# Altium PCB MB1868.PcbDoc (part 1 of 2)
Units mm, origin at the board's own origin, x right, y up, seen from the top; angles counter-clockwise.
Board outline 59.55 x 30 mm, 2 copper layers (Top Layer, Bottom Layer), stack 1.499 mm thick; 74 components, 54 nets, 296 pads, 368 vias.
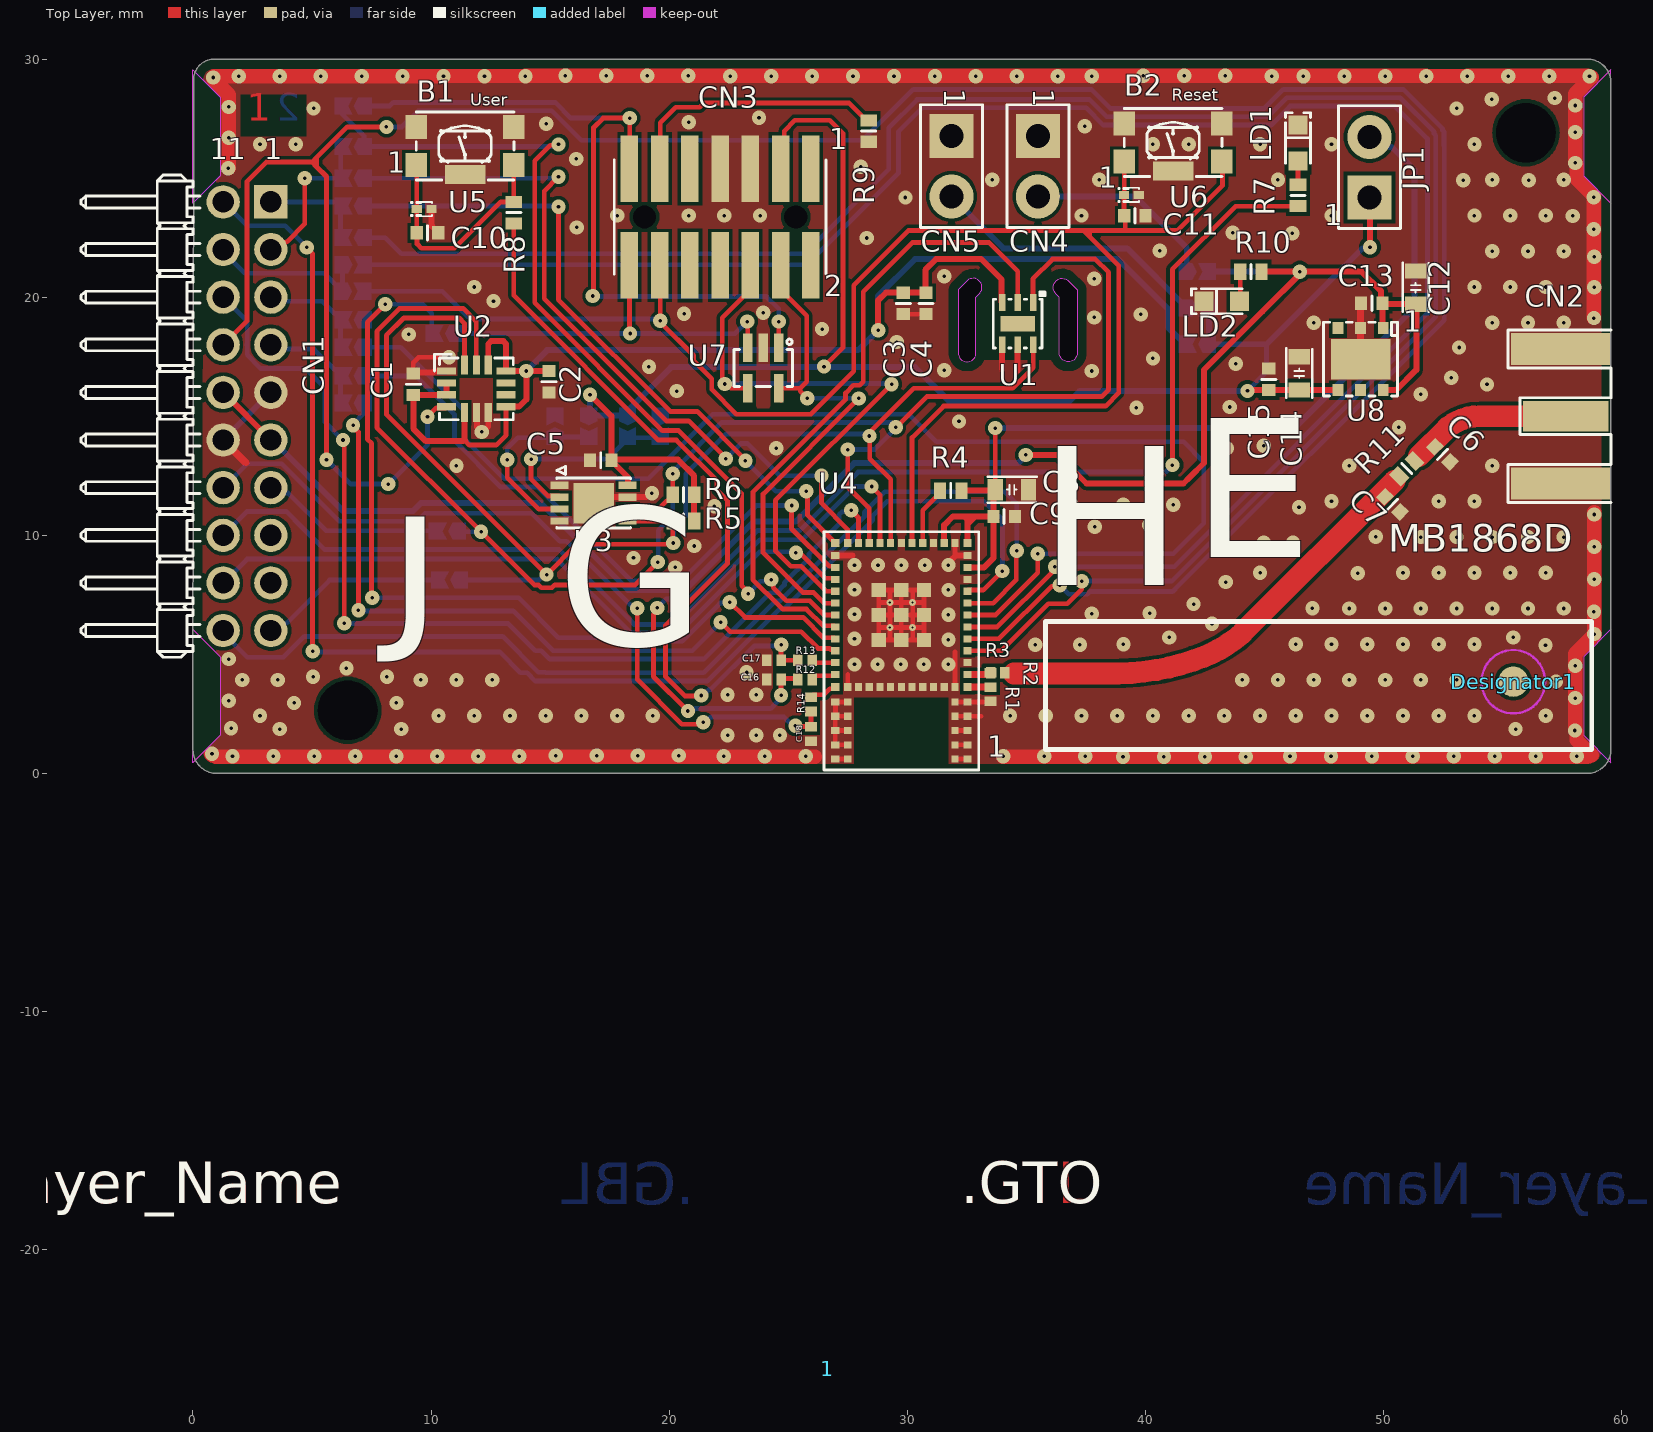
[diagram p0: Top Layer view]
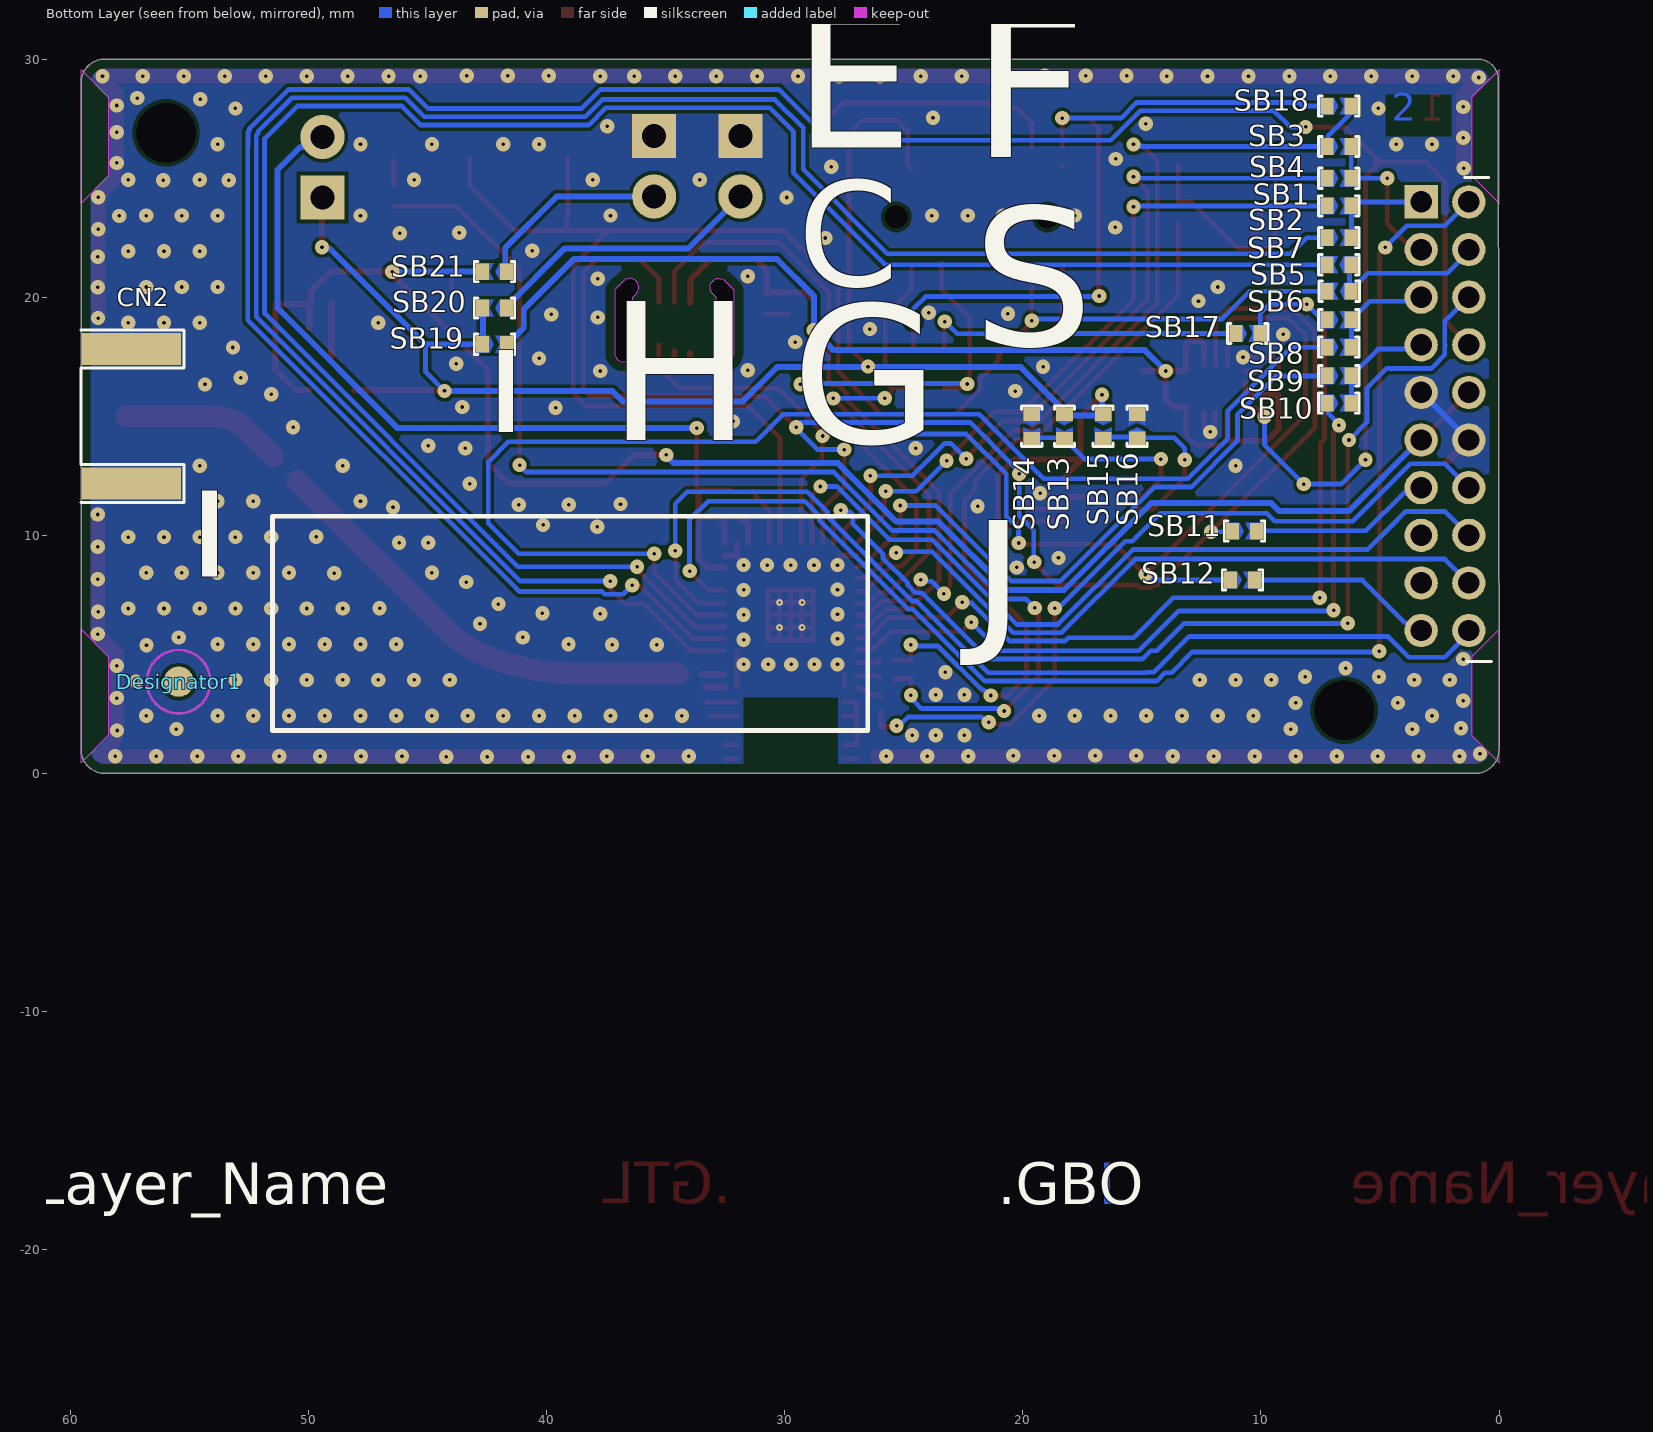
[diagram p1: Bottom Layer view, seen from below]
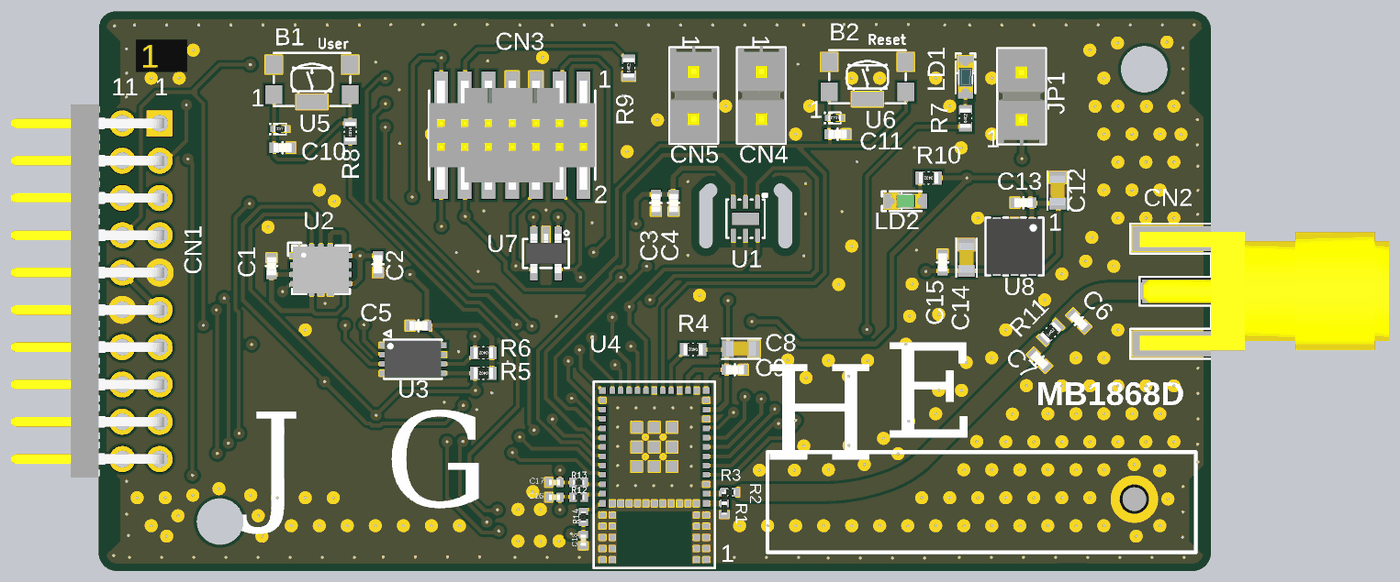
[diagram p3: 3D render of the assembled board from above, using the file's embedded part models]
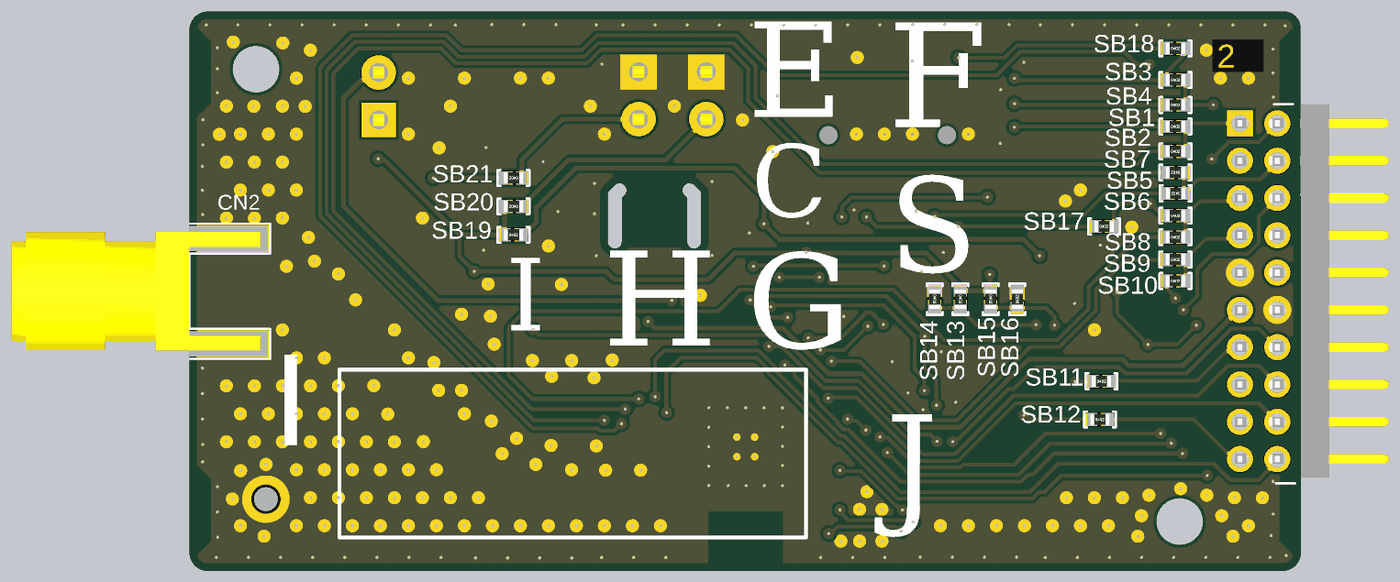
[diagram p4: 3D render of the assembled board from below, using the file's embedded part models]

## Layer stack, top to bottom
Top Solder: solder mask 0.02, Solder Resist, Dk 4.2
Top Layer: signal copper 0.0175
Dielectric 2: core 1.464, 8 x 7628, Dk 4.2
Bottom Layer: signal copper 0.0175
Bottom Solder: solder mask 0.02, Solder Resist, Dk 4.2

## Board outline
0,1 0.025,29.124 cw(c0.902,29.124) 0.902,30 58.55,30 cw(c58.55,29) 59.55,29 59.55,1 cw(c58.55,1) 58.55,0 1,0 cw(c1,1)
cut-out: 32.884,20.007 33.024,20.147 ccw(c32.759,20.412) 33.134,20.412 ccw(c32.772,20.412) 33.028,20.668 32.984,20.712 ccw(c32.803,20.531) 32.803,20.787 32.759,20.787 ccw(c32.759,20.412) 32.494,20.677 32.134,20.317 32.134,17.662 ccw(c32.509,17.662) 32.509,17.287 ccw(c32.509,17.662) 32.884,17.662
cut-out: 36.384,20.007 36.244,20.147 cw(c36.509,20.412) 36.134,20.412 cw(c36.496,20.412) 36.24,20.668 36.284,20.712 cw(c36.465,20.531) 36.465,20.787 36.509,20.787 cw(c36.509,20.412) 36.774,20.677 37.134,20.317 37.134,17.662 cw(c36.759,17.662) 36.759,17.287 cw(c36.759,17.662) 36.384,17.662

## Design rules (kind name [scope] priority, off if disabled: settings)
BoardOutlineClearance [All and not (InComponent('CN1', 'CN2') or IsText)] p1: gap=0.4 ignorepadtopadclearanceinfootprint=FALSE
Clearance Clearance_Keepout [IsKeepout] p1: gap=0 ignorepadtopadclearanceinfootprint=TRUE
Clearance Clearance_RF_SINGLE-50R_L1-2 [InNetClass('NC_RF_SINGLE-50R_L1-2')] p2: gap=0.2 ignorepadtopadclearanceinfootprint=TRUE except(0.15: SMDPad-SMDPad SMDPad-Region; 0.17: Region-Region)
Clearance Clearance_Default [All] p3: gap=0.15 ignorepadtopadclearanceinfootprint=TRUE
ComponentClearance [All] p1 off: gap=0.025 collisioncheckmode=3 verticalgap=2540 showdistances=TRUE
FanoutControl Fanout_BGA [IsBGA] p1: bgadir=Out bgaviamode=Closest fanoutstyle=Auto fanoutdirection=Alternating viagrid=0.025 // Fanout_BGA (Default Rule)
FanoutControl Fanout_LCC [IsLCC] p2: bgadir=Out bgaviamode=Closest fanoutstyle=Auto fanoutdirection=Alternating viagrid=0.025 // Fanout_LCC (Default Rule)
FanoutControl Fanout_SOIC [IsSOIC] p3: bgadir=Out bgaviamode=Closest fanoutstyle=Auto fanoutdirection=Alternating viagrid=0.025 // Fanout_SOIC (Default Rule)
FanoutControl Fanout_Small [(CompPinCount < 5)] p4: bgadir=Out bgaviamode=Closest fanoutstyle=Auto fanoutdirection=OutThenIn viagrid=0.025 // Fanout_Small (Default Rule)
FanoutControl Fanout_Default [All] p5: bgadir=Out bgaviamode=Closest fanoutstyle=Auto fanoutdirection=Alternating viagrid=0.025 // Fanout_Default (Default Rule)
Height [All] p1 off: minheight=0 maxheight=100 prefheight=0.5
HoleSize [All] p1: absolutevalues=TRUE maxlimit=10 minlimit=0.1 maxpercent=80.000 minpercent=20.000
HoleToHoleClearance [All] p1: gap=0.25 allowstackedmicrovias=TRUE
MinimumSolderMaskSliver [All] p1: minsoldermaskwidth=0.1
PlaneClearance [All] p1: clearance=0.6
PolygonConnect PolygonConnect__Default [All] p1: connectstyle=Direct reliefconductorwidth=0.3 reliefentries=2 polygonreliefangle="90 Angle" airgapwidth=0.3
RoutingVias [All] p1: holewidth=0.15 width=0.5 viastyle="Through Hole" minholewidth=0.1 minwidth=0.3 maxholewidth=0.3 maxwidth=0.6
SilkToSilkClearance [All] p1: silktosilkclearance=0.05
SilkToSolderMaskClearance [IsPad] p1: minsilkscreentomaskgap=0.05 clearancetoexposedcopper=TRUE
SolderMaskExpansion SolderMaskExpansion_Via [IsVia] p1: expansion=0.075 istentingtop=FALSE soldermaskfromhole=TRUE
SolderMaskExpansion [All] p2: expansion=0.05 istentingtop=FALSE
UnRoutedNet [All] p1: checkbadconnections=TRUE
Width Width_RF_SINGLE-50R_L1-2 [InNetClass('NC_RF_SINGLE-50R_L1-2')] p1: maxlimit=0.914 minlimit=0.3 preferedwidth=0.914 minimp=50.000000 maximp=50.000000 favimp=50.000000
Width Width_ALIMS [InNetClass('NC_POWERS')] p2: maxlimit=10 minlimit=0.2 preferedwidth=0.3
Width Width_Default [All] p3: maxlimit=10 minlimit=0.2 preferedwidth=0.2
16 further rules are at their usual default settings.

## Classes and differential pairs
component class "U_STMOD+ interface": CN1 SB1 SB2 SB3 SB4 SB5 SB6 SB7 SB8 SB9 SB10 SB11 SB12
component class U_STM32WB1M: B1 B2 C6 C7 C8 C9 C10 C11 C16 C17 C18 CN2 HW20 LD1 R1 R2 R3 R4 R5 R6 R7 R8 R11 R12 R13 R14 SB17 SB18 U4 U5 U6
component class U_Mems: C1 C2 C3 C4 C5 SB13 SB14 SB15 SB16 U1 U2 U3
component class "U_Board supply": C12 C13 C14 C15 CN3 CN4 CN5 HW5 HW6 JP1 LD2 R9 R10 SB19 SB20 SB21 U7 U8

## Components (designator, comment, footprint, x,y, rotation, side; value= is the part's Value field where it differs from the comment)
1 "Comment" Sheetbox_2L2S -18.45,-30.35 r0 top
B1 "" SWI_C&K_Y78B23110FP__ITT_KMR231GLFS 11.425,26.35 r180 top value=KMR231GLFS
B2 "" SWI_C&K_Y78B23110FP__ITT_KMR231GLFS 41.159,26.497 r180 top value=KMR231GLFS
C1 "Capacitor" C0402 9.255,16.345 r270 top value=100nF
C2 "Capacitor" C0402 14.95,16.45 r90 top value=100nF
C3 "Capacitor" C0402 29.834,19.737 r90 top value=2.2uF
C4 "Capacitor" C0402 30.784,19.737 r90 top value=100nF
C5 "Capacitor" C0402 17.125,13.15 r0 top value=100nF
C6 "Capacitor" C0402 52.475,13.4 r315 top value=NC
C7 "Capacitor" C0402 50.375,11.3 r315 top value=NC
C8 "" C0603 34.39,11.915 r180 top value=4.7uF
C9 "Capacitor" C0402 34.065,10.79 r180 top value=100nF
C10 "Capacitor" C0402 9.85,22.7 r180 top value=100nF
C11 "Capacitor" C0402 39.559,23.418 r180 top value=100nF
C12 "" C0603 51.35,20.4 r270 top value=1uF
C13 "" C0402 49.509,19.747 r0 top value=100nF
C14 "" C0603 46.459,16.797 r270 top value=1uF
C15 "" C0402 45.184,16.547 r270 top value=100nF
C16 "Capacitor" C0201_H0P3 24.4,3.95 r0 top value=2.7pF
C17 "Capacitor" C0201_H0P3 24.4,4.75 r0 top value=2.7pF
C18 "Capacitor" C0201_H0P3 25.95,1.65 r90 top value=2.7pF
CN1 "Header 10x2 STMod+" CON_SAMTEC_TMM-110-01-L-D-RA__STMOD+ 0,15 r270 top
CN2 "" CON_SAMTEC_SMA-J-P-X-ST-EM1 59.55,15 r90 top locked value=SMA-J-P-H-ST-EM1
CN3 "Header 7x2" CON_STDC14_Receiver_SMALL 22.14,23.368 r180 top
CN4 "" CON_SAMTEC_TSW-102-07-G-S 35.484,25.499 r270 top value="Shunt Not Fitted" (schematic designator JP4)
CN5 "" CON_SAMTEC_TSW-102-07-G-S 31.859,25.499 r270 top value="Shunt Not Fitted" (schematic designator JP5)
Designator1 "Comment" "MIRECMS (dia1.27-zi2.54)" 55.45,3.85 r0 top
Designator1 "Comment" "MIRECMS (dia1.27-zi2.54)" 55.45,3.85 r180 bottom
JP1 "" CON_SAMTEC_TSW-102-07-G-S 49.409,25.457 r90 top value="Shunt Fitted"
LD1 "" LED_0603_OSRAM_LB-Q39G-L2OO-35-1_BLUE_1A2K_H0P4 46.409,26.472 r90 top value=BLUE
LD2 "" LED_0603_OSRAM_LG-Q396-PS-35_GREEN_1A2K_H0P4 43.209,19.828 r180 top value=GREEN
R1 "Resistor" R0201_H0P23 33.5,3.325 r270 top value=NC
R2 "Resistor" R0201_H0P23 33.5,3.925 r270 top value=0R
R3 "Resistor" R0201_H0P23 33.8,4.225 r180 top value=NC
R4 "" R0402 31.825,11.875 r180 top value=NC
R5 "Resistor" R0402 20.6,10.6 r180 top value=2K2
R6 "Resistor" R0402 20.6,11.7 r180 top value=2K2
R7 "" R0402 46.406,24.272 r90 top value=120R
R8 "" R0402 13.475,23.55 r270 top value=1K
R9 "" R0402 28.375,26.975 r90 top value=100R
R10 "" R0402 44.43,21.072 r180 top value=620R
R11 "Resistor" R0402 50.975,12.8 r45 top value=NC
R12 "Resistor" R0201_H0P23 25.7,3.95 r0 top value=15R
R13 "Resistor" R0201_H0P23 25.7,4.75 r0 top value=15R
R14 "Resistor" R0201_H0P23 25.95,2.9 r90 top value=15R
SB1 "SB_OFF" SOLDER-BRIDGE_R0402-0R 6.725,23.833 r180 bottom
SB2 "SB_ON" SOLDER-BRIDGE_R0402-0R 6.725,22.5 r180 bottom
SB3 "SB_OFF" SOLDER-BRIDGE_R0402-0R 6.725,26.325 r180 bottom
SB4 "SB_ON" SOLDER-BRIDGE_R0402-0R 6.725,24.992 r180 bottom
SB5 "SB_ON" SOLDER-BRIDGE_R0402-0R 6.716,20.25 r0 bottom
SB6 "SB_OFF" SOLDER-BRIDGE_R0402-0R 6.725,19.05 r180 bottom
SB7 "SB_OFF" SOLDER-BRIDGE_R0402-0R 6.725,21.362 r0 bottom
SB8 "SB_ON" SOLDER-BRIDGE_R0402-0R 6.725,17.9 r180 bottom
SB9 "SB_OFF" SOLDER-BRIDGE_R0402-0R 6.725,16.7 r180 bottom
SB10 "SB_ON" SOLDER-BRIDGE_R0402-0R 6.725,15.55 r180 bottom
SB11 "SB_ON" SOLDER-BRIDGE_R0402-0R 10.687,10.175 r180 bottom
SB12 "SB_ON" SOLDER-BRIDGE_R0402-0R 10.775,8.125 r180 bottom
SB13 "SB_ON" SOLDER-BRIDGE_R0402-0R 18.25,14.575 r270 bottom
SB14 "SB_OFF" SOLDER-BRIDGE_R0402-0R 19.625,14.575 r270 bottom
SB15 "SB_ON" SOLDER-BRIDGE_R0402-0R 16.625,14.575 r270 bottom
SB16 "SB_OFF" SOLDER-BRIDGE_R0402-0R 15.2,14.575 r90 bottom
SB17 "SB_ON" SOLDER-BRIDGE_R0402-0R 10.55,18.475 r180 bottom
SB18 "SB_ON" SOLDER-BRIDGE_R0402-0R 6.725,28.023 r180 bottom
SB19 "SB_ON" SOLDER-BRIDGE_R0402-0R 42.184,18.022 r180 bottom
SB20 "SB_OFF" SOLDER-BRIDGE_R0402-0R 42.184,19.547 r0 bottom
SB21 "SB_ON" SOLDER-BRIDGE_R0402-0R 42.184,21.072 r0 bottom
U1 "STTS22H" ICC_UDFN6-EPAD_2X2_P065 34.634,18.887 r180 top
U2 "ISM330DHCX" ICC_LGA14_3X2P5_P050 11.9,16.15 r0 top
U3 "M24128-DFMC6TP" ICC_DFN8-EPAD_2X3_P050 16.825,11.35 r90 top value=M24256-DFMC6TG
U4 "STM32WB1M" ICC_LBA77_6P5X10_P0P45 29.75,5.15 r180 top locked
U5 "" ESD_ST0201 9.712,23.7 r0 top value=ESDALC6V1-1U2
U6 "" ESD_ST0201 39.409,24.293 r0 top value=ESDALC6V1-1U2
U7 "" ESD_SOT323-5L 23.95,17.025 r180 top value=ESDALC6V1W5
U8 "" ICC_DFN6-EPAD_3X3_P095 49.034,17.397 r180 top value=LD39050PU33R

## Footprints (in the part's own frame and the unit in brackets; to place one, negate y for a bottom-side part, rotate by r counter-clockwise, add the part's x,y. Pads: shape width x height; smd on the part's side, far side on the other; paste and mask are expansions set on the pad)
C0201_H0P3 [mm] "MCD-00699"
  rect 0.4x0.5 smd mask+0.05: 1(-0.3,0) 2(0.3,0)
  body extent -0.32,-0.17 0.32,0.17, height 0.33
C0402 [mm]
  rect 0.51x0.56 smd mask+0.05: 1(-0.45,0) 2(0.45,0)
  silkscreen extent 0,-0.3 0,0.3, body extent -0.5,-0.3 0.5,0.3, height 0.4
C0603 [mm]
  rect 0.64x0.89 smd mask+0.05: 1(-0.7,0) 2(0.7,0)
  silkscreen extent -1.05,-0.55 1.02,0.55, body extent -0.9,-0.5 0.9,0.5, height 1.4
CON_SAMTEC_SMA-J-P-X-ST-EM1 [mm]
  rect 1.27x3.6 smd mask+0.05: 1(0,1.9)
  rect 1.35x4.2 smd mask+0.05: 2(-2.825,2.1) 3(2.825,2.1)
  rect 1.35x4.2 smd far side mask+0.05: 4(2.825,2.1) 5(-2.825,2.1)
  silkscreen extent -3.62,0 3.62,4.33, body extent -3.17,-9.53 3.17,3.8, height 3.55
CON_SAMTEC_TMM-110-01-L-D-RA__STMOD+ [mm]
  rect 1.4x1.4 hole 0.9 mask+0.05: 1(-9,3.27)
  round 1.4 hole 0.9 mask+0.05: 2(-7,3.27) 3(-5,3.27) 4(-3,3.27) 5(-1,3.27) 6(1,3.27) 7(3,3.27) 8(5,3.27) 9(7,3.27) 10(9,3.27) 11(-9,1.27) 12(-7,1.27) 13(-5,1.27) 14(-3,1.27) 15(-1,1.27) 16(1,1.27) 17(3,1.27) 18(5,1.27) 19(7,1.27) 20(9,1.27)
  silkscreen extent -10.12,-4.7 10.13,0.3, body extent -10.15,-6.35 10.15,3.52, height 4
CON_SAMTEC_TSW-102-07-G-S [mm]
  rect 1.85x1.85 / inner round 1.85 / far side rect 1.85x1.85 hole 1 mask+0.05: 1(-1.27,0)
  round 1.85 hole 1 mask+0.05: 2(1.27,0)
  silkscreen extent -2.58,-1.3 2.58,1.3, body extent -2.67,-1.3 2.58,1.3, height 8.38
CON_STDC14_Receiver_SMALL [mm] "compatible with Samtec FTSH-107-01-L-DV,-K,-A,-P"
  round 0 hole 0.97 unplated mask+0.05: 0(-3.175,0) 0(3.175,0)
  rect 0.74x2.79 smd mask+0.05: 1(-3.81,-2.032) 2(-3.81,2.032) 3(-2.54,-2.032) 4(-2.54,2.032) 5(-1.27,-2.032) 6(-1.27,2.032) 7(0,-2.032) 8(0,2.032) 9(1.27,-2.032) 10(1.27,2.032) 11(2.54,-2.032) 12(2.54,2.032) 13(3.81,-2.032) 14(3.81,2.032)
  silkscreen extent -4.44,-2.39 4.44,2.39, body extent -4.45,-2.92 4.45,2.92, height 6.6
ESD_SOT323-5L [mm]
  rect 0.4x1.2 smd mask+0.05: 1(-0.65,-0.85) 2(0,-0.85) 3(0.65,-0.85) 4(0.65,0.85) 5(-0.65,0.85)
  silkscreen extent -1.22,-1.21 1.22,0.77, body extent -1.15,-1.05 1.15,1.05, height 1.1
ESD_ST0201 [mm]
  rect 0.425x0.33 smd mask+0.05: 1(-0.312,0) 2(0.312,0)
  silkscreen extent -0.55,-0.3 0.33,0.3, body extent -0.34,-0.18 0.34,0.18, height 0.34
ICC_DFN6-EPAD_3X3_P095 [mm]
  rect 0.45x0.5 smd mask+0.05: 1(-0.95,-1.3) 2(0,-1.3) 3(0.95,-1.3) 4(0.95,1.3) 5(0,1.3) 6(-0.95,1.3)
  rect 2.5x1.7 smd mask+0.05: EP(0,0)
  silkscreen extent -1.55,-1.55 1.55,1.55, body extent -1.55,-1.55 1.55,1.55, height 1
ICC_DFN8-EPAD_2X3_P050 [mm]
  rect 0.3x0.75 smd mask+0.05: 1(0.75,1.425) 2(0.25,1.425) 3(-0.25,1.425) 4(-0.75,1.425) 5(-0.75,-1.425) 6(-0.25,-1.425) 7(0.25,-1.425) 8(0.75,-1.425)
  rect 1.7x1.7 smd mask+0.05: EP(0,0)
  silkscreen extent -1.05,-1.55 1.55,1.55, body extent -1.05,-1.55 1.05,1.55, height 0.9
ICC_LBA77_6P5X10_P0P45 [mm] "MCD-02528"
  rect 0.35x0.3 smd mask+0.05: 1(-2.775,4.55) 2(-2.775,3.95) 3(-2.775,3.35) 4(-2.775,2.75) 5(-2.775,2.15) 7(-2.775,1) 8(-2.775,0.5) 9(-2.775,0) 10(-2.775,-0.5) 11(-2.775,-1) 12(-2.775,-1.5) 13(-2.775,-2) 14(-2.775,-2.5) 15(-2.775,-3) 16(-2.775,-3.5) 17(-2.775,-4) 31(2.775,-4) 32(2.775,-3.5) 33(2.775,-3) 34(2.775,-2.5) 35(2.775,-2) 36(2.775,-1.5) 37(2.775,-1) 38(2.775,-0.5) 39(2.775,0) 40(2.775,0.5) 41(2.775,1) 43(2.775,2.15) 44(2.775,2.75) 45(2.775,3.35) 46(2.775,3.95) 47(2.775,4.55)
  rect 0.35x0.35 smd mask+0.05: 6(-2.775,1.525) 18(-2.775,-4.525) 30(2.775,-4.525) 42(2.775,1.525)
  rect 0.3x0.35 smd mask+0.05: 19(-2.25,-4.525) 20(-1.8,-4.525) 21(-1.35,-4.525) 22(-0.9,-4.525) 23(-0.45,-4.525) 24(0,-4.525) 25(0.45,-4.525) 26(0.9,-4.525) 27(1.35,-4.525) 28(1.8,-4.525) 29(2.25,-4.525) 53(2.25,1.525) 54(1.8,1.525) 55(1.35,1.525) 56(0.9,1.525) 57(0.45,1.525) 58(0,1.525) 59(-0.45,1.525) 60(-0.9,1.525) 61(-1.35,1.525) 62(-1.8,1.525) 63(-2.25,1.525)
  rect 0.3x0.3 smd mask+0.05: 48(2.25,4.55) 49(2.25,3.95) 50(2.25,3.35) 51(2.25,2.75) 52(2.25,2.15) 64(-2.25,2.15) 65(-2.25,2.75) 66(-2.25,3.35) 67(-2.25,3.95) 68(-2.25,4.55)
  rect 0.6x0.6 smd mask+0.05: 69(-0.95,-0.45) 70(-0.95,-1.5) 71(-0.95,-2.55) 72(0,-2.55) 73(0,-1.5) 74(0,-0.45) 75(0.95,-0.45) 76(0.95,-1.5) 77(0.95,-2.55)
  silkscreen extent -3.25,-5 3.25,5, body extent -3.25,-5 3.25,5, height 1.4
ICC_LGA14_3X2P5_P050 [mm] "MCD-01387"
  rect 0.8x0.3 smd mask+0.05: 1(-1.25,0.75) 2(-1.25,0.25) 3(-1.25,-0.25) 4(-1.25,-0.75) 8(1.25,-0.75) 9(1.25,-0.25) 10(1.25,0.25) 11(1.25,0.75)
  rect 0.3x0.8 smd mask+0.05: 5(-0.5,-1) 6(0,-1) 7(0.5,-1) 12(0.5,1) 13(0,1) 14(-0.5,1)
  silkscreen extent -1.75,-1.3 1.55,1.45, body extent -1.55,-1.3 1.55,1.3, height 0.86
ICC_UDFN6-EPAD_2X2_P065 [mm] "MCD-02159"
  rect 0.27x0.7 smd mask+0.05: 1(-0.65,-0.89) 2(0,-0.89) 3(0.65,-0.89) 4(0.65,0.89) 5(0,0.89) 6(-0.65,0.89)
  rect 1.45x0.65 smd mask+0.05: 7(0,0)
  silkscreen extent -1.15,-1.33 1.02,1.02, body extent -1.03,-1.03 1.02,1.02, height 0.56
LED_0603_OSRAM_LB-Q39G-L2OO-35-1_BLUE_1A2K_H0P4 [mm]
  rect 0.8x0.8 smd mask+0.05: 1(-0.75,0) 2(0.75,0)
  silkscreen extent -0.85,-0.53 1.28,0.53, body extent -0.85,-0.45 0.85,0.45, height 0.6
LED_0603_OSRAM_LG-Q396-PS-35_GREEN_1A2K_H0P4 [mm]
  rect 0.8x0.8 smd mask+0.05: 1(-0.75,0) 2(0.75,0)
  silkscreen extent -0.85,-0.53 1.28,0.53, body extent -0.85,-0.45 0.85,0.45, height 0.6
"MIRECMS (dia1.27-zi2.54)" [mm]
  round 1.27 smd paste+0 mask+0.635: 1(0,0)
  Top Layer keep-out circle w0.1: c0,0 r1.334
R0201_H0P23 [mm] "MCD-00702"
  rect 0.4x0.5 smd mask+0.05: 1(-0.3,0) 2(0.3,0)
  body extent -0.32,-0.17 0.32,0.17, height 0.26
R0402 [mm]
  rect 0.51x0.7 smd mask+0.05: 1(-0.45,0) 2(0.45,0)
  silkscreen extent 0,-0.3 0,0.3, body extent -0.52,-0.3 0.52,0.3, height 0.4
Sheetbox_2L2S [mil] "Sheetbox 2 layers / 2 silkscreens"
  round 20 on Mech16: 1(813.78,210.69) 1(2736.9,210.69)
SOLDER-BRIDGE_R0402-0R [mm] "MCD-01619"
  rect 0.55x0.7 smd paste-10 mask-5: 1(-0.5,0) 2(0.505,0)
  Top Layer region: 0.038,-0.35 0.212,0 0.038,0.35 0.775,0.35 0.775,-0.35
  Top Layer region: -0.775,0.35 -0.775,-0.35 -0.212,-0.35 -0.038,0 -0.212,0.35
  silkscreen extent -0.85,-0.43 0.85,0.43, body extent -0.52,-0.3 0.52,0.3, height 0.35
SWI_C&K_Y78B23110FP__ITT_KMR231GLFS [mm] "MCD-00715"
  rect 0.9x1 smd mask+0.05: 1(2.05,0.8) 2(2.05,-0.8) 3(-2.05,0.8) 4(-2.05,-0.8)
  rect 1.7x0.8 smd mask+0.05: 5(0,1.2)
  silkscreen extent -2.05,-1.43 2.05,1.43, body extent -2.3,-1.5 2.3,1.5, height 2.1

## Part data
1: library part MCD-01965
B1 B2: library part MCD-01485, "Microminiature Tact Switch for SMT - KMR 2 Series - 1.9 mm height", Manufacturer=C&K, Manufacturer_Part_Number=KMR231GLFS
C1 C2 C4 C5 C9 C10 C11: library part MCD-00006, "Capacitor, MLCC, 100nF, 16V, X7R, +/-10%, 0402, T=0.5mm", Manufacturer=YAGEO, Manufacturer_Part_Number=CC0402KRX7R7BB104, Package=0402
C3: library part MCD-01823, "Capacitor, MLCC, 2.2uF, 6V3, X5R,+/-10%, 0402, T=0.5mm", Alternate_Manufacturer=N/A, Manufacturer=MURATA, Manufacturer_Part_Number=GRM155R60J225KE95D, Package=0402
C6 C7: library part MCD-01995, "Capacitor, MLCC, 22pF, 50V, C0G, +/-5%, 0402, T=0.5mm", Alternate_Manufacturer=N/A, Manufacturer=TDK, Manufacturer_Part_Number=C1005NP01H220J050BA, Package=0402
C8: library part MCD-00009, "Capacitor, MLCC, 4.7uF, 16V, X5R, 10%, 0603, T=0.8mm", Manufacturer=YAGEO, Manufacturer_Part_Number=CC0603KRX5R7BB475, Package=C0603
C12 C14: library part MCD-00010, "Capacitor, MLCC, 1uF, 16V, X5R, 10%, 0603, T=0,8mm", Manufacturer=YAGEO, Manufacturer_Part_Number=CC0603KRX5R7BB105, Package=C0603
C13 C15: library part MCD-00102, "Capacitor, MLCC, 100nF, 16V, X7R, 10%, 0402, T=0,5mm", Alternate_Manufacturer=MURATA, Alternate_Manufacturer_Part_Number=GCM155R71C104KA55D, Manufacturer=YAGEO, Manufacturer_Part_Number=CC0402KRX7R7BB104, Package=C0402
C16 C17 C18: library part MCD-0228?, "Capacitor, MLCC, 2.7pF, 50V, NPO, +-0.05pF, 0201, T=0.3mm\".", Manufacturer=MURATA, Manufacturer_Part_Number=GRM0335C1H2R7BA01D, Package=0201
CN1: library part MCD-00288, "Header 10x2, 2mm, RA, TH, Height 3.20mm/3.50mm", Manufacturer=SAMTEC, Manufacturer_Part_Number=TMM-110-01-L-D-RA
CN2: library part MCD-00279, "RF SMA connector PCB edge", Manufacturer=SAMTEC, Manufacturer_Part_Number=SMA-J-P-H-ST-EM1
CN3: library part MCD-00639, "Header, 7x2, 1.27mm, VR, SMD, T=5.97mm", Alternate_Manufacturer=N/A, Manufacturer=SAMTEC, Manufacturer_Part_Number=FTSH-107-01-L-DV-K
CN4 CN5 JP1: library part MCD-00683, "Header, 2x1, 2,54mm, VR, TH, Height 5.84mm/2.54mm - Shunt Fitted by default", Manufacturer=SAMTEC, Manufacturer_Part_Number=TSW-102-07-x-S
LD1: library part MCD-00585, "LED Blue, 0603 SMD, Forward Voltage Min=2,8V, Max=3,8V", Manufacturer="OSRAM OPTO SEMICONDUCTORS", Manufacturer_Part_Number="LB Q39G-L2OO-35-1", Package="LED 0603"
LD2: library part MCD-00588, "LED Green, 0603 SMD, Forward Voltage Typ=2V, Max=2.5V", Alternate_Manufacturer="VISHAY SEMICONDUCTOR OPTO DIVISION", Alternate_Manufacturer_Part_Number=VLMTG1300-GS08, Manufacturer="OSRAM OPTO SEMICONDUCTORS", Manufacturer_Part_Number="LG Q396-PS-35", Package="LED 0603"
R1 R3: library part MCD-02253, "Resistor, 0R, 0201, +/-1%, 1/20W", Alternate_Manufacturer=N/A, Manufacturer=YAGEO, Manufacturer_Part_Number=RC0201FR-070RL, Package=0201
R2: library part MCD-02450, "Resistor, 0R, 0201, 1/20W", Manufacturer=YAGEO, Manufacturer_Part_Number=RC0201JR-070RP, Package=0201
R4 R7: library part MCD-00194, "Resistor,120R,0402,1%,1/16W", Manufacturer=YAGEO, Manufacturer_Part_Number=RC0402FR-07120RL, Package=R0402
R5 R6: library part MCD-00057, "Resistor, 2K2, 0402, +/-1%, 1/16W", Manufacturer=YAGEO, Manufacturer_Part_Number=RC0402FR-072K2L, Package=0402
R8: library part MCD-00061, "Resistor,1K,0402,1%,1/16W", Manufacturer=YAGEO, Manufacturer_Part_Number=RC0402FR-071KL, Package=R0402
R9: library part MCD-00119, "Resistor,100R,0402,1%,1/16W", Manufacturer=YAGEO, Manufacturer_Part_Number=RC0402FR-07100RL, Package=R0402
R10: library part MCD-00499, "Resistor,620R,0402,1%,1/16W", Manufacturer=YAGEO, Manufacturer_Part_Number=RC0402FR-07620RL, Package=R0402
R11: library part MCD-02253, "Resistor, 0R, 0402, +/-1%, 1/16W", Alternate_Manufacturer=N/A, Manufacturer=YAGEO, Manufacturer_Part_Number=RC0402JR-070RL, Package=0402
R12 R13 R14: library part MCD-03509, "Resistor, 15R, 0201, 1%, 1/20W", Manufacturer=YAGEO, Manufacturer_Part_Number=RC0201FR-0715RL, Package=0201
SB1 SB3 SB6 SB7 SB9 SB14 SB16 SB20: library part MCD-02162, "Solder Bridge 0402 OFF", Alternate_Manufacturer=N/A, Manufacturer=YAGEO, Manufacturer_Part_Number=RC0402JR-070RL, Package=SB0402
SB2 SB4 SB5 SB8 SB10 SB11 SB12 SB13 SB15 SB17 SB18 SB19 SB21: library part MCD-01618, "Solder Bridge 0402 ON", Manufacturer=YAGEO, Manufacturer_Part_Number=RC0402JR-070RL, Package=SB0402
U1: library part MCD-02159, "temperature sensor", Alternate_Manufacturer=N/A, Manufacturer=STMICROELECTRONICS, Manufacturer_HQ_COO=EU, Package="UDFN 6-pins 2x2x0.5mm"
U2: library part MCD-02160, "iNEMO inertial module: 3D accelerometer and 3D gyroscope, with digital output for industrial applications", Alternate_Manufacturer=N/A, Manufacturer=STMICROELECTRONICS, Manufacturer_HQ_COO=EU, Manufacturer_Part_Number=ISM330DHCXTR, Package=LGA-14L
U3: library part MCD-01871, "I2C Memory 3V3, 256Kbits, 2x3,0.55mm, UFDFPN8", Manufacturer=STMICROELECTRONICS, Manufacturer_HQ_COO=EU, Manufacturer_Part_Number=M24256-DFMC6TG
U4: library part MCD-02528, "STM32 BLE module based on STM32WB15", Alternate_Manufacturer=N/A, Manufacturer=STMICROELECTRONICS, Package=LBA77
U5 U6: library part MCD-00170, "ESD protection 6V1", Manufacturer=STMICROELECTRONICS, Manufacturer_Part_Number=ESDALC6V1-1U2
U7: library part MCD-00136, "Dual Transil array for ESD protection", Manufacturer=STMICROELECTRONICS, Manufacturer_Part_Number=ESDALC6V1W5
U8: library part MCD-00215, "Low quiescent current and low noise voltage regulators", Manufacturer=STMICROELECTRONICS, Manufacturer_Part_Number=LD39050PU33R, Package="DFN6 3x3mm"

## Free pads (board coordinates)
  round 0 hole 2.5 unplated: 2(6.5,2.65) 2(55.977,26.903)

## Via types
v1: diameter 0.6, hole 0.15, Top Layer to Bottom Layer, 339 vias
v2: diameter 0.6, hole 0.15, Top Layer to Bottom Layer, tented both sides, 25 vias
v3: diameter 0.3, hole 0.1, Top Layer to Bottom Layer, 4 vias

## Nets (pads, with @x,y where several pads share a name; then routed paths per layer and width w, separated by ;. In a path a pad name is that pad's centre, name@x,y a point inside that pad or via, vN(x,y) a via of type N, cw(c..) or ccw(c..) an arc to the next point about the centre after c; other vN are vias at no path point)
3V3: C5.2 C14.2 C15.2 CN3.3 JP1.1 R5.1 R6.1 SB13.1 SB15.1 SB19.1 SB20.2 U3.8 U8.4 | length 73.3
  Top Layer w0.2: CN3.3@24.68,25.4 24.828,25.548 24.828,26.978 25.275,27.425 26.743,27.425 27.294,26.874 27.294,17.88 v1(26.5,17.085) ; JP1.1@49.409,24.187 JP1.1@49.432,24.164
  Top Layer w0.25: v1(16.675,15.9) 17.575,15 C5.2@17.575,13.15 17.575,13.175 20.368,13.175 21.05,12.493 R6.1@21.05,11.7 R5.1@21.05,10.6 ; C5.2@17.575,13.125 17.73,12.97 18.267,12.433 18.267,12.15 18.25,12.133 U3.8@18.25,12.1 ; v1(44.288,16.061) 44.324,16.097 C14.2@46.459,16.097 U8.4@48.084,16.097 ; v1(49.432,22.099) JP1.1@49.432,24.164
  Bottom Layer w0.2: v1(44.288,16.061) 45.084,16.858 45.084,18.022
  Bottom Layer w0.25: SB15.1@16.625,15.026 16.675,15.076 v1(16.675,15.9) ; SB15.1@16.626,15.025 18.085,15.025 SB13.1@18.25,15.025 ; SB13.1@18.085,15.06 20.083,17.058 26.5,17.058 30.323,17.058 31.756,15.625 36.8,15.625 37.236,16.061 v1(44.288,16.061) ; SB19.1@42.634,18.022 SB19.1@42.672,18.022 ; SB20.2@42.672,19.472 42.672,18.197 SB19.1@42.672,18.022 ; SB20.2@42.71,19.547 SB20.2@42.785,19.472 ; v1(49.432,22.099) 49.384,22.052 49.114,22.052 45.084,18.022 SB19.1@42.672,18.022
3V3_MEMs: C1.2 C2.2 C3.2 C4.2 SB19.2 U1.3 U2.2 U2.3 U2.5 U2.8 U2.11 U2.12 | length 57.9
  Top Layer w0.2: 11.407,13.993 11.609,13.791 12.741,13.791 13.15,14.2 U2.8@13.15,15.4
  Top Layer w0.25: U2.2@10.65,16.4 U2.3@10.65,15.9 10.645,15.895 C1.2@9.255,15.895 9.255,14.475 9.78,13.95 11.364,13.95 11.407,13.993 11.419,14.006 ; 11.4,14.025 U2.5@11.4,15.15 ; U2.12@12.4,17.15 12.4,18.033 12.517,18.15 13.033,18.15 13.15,18.033 U2.11@13.15,16.9 v1(14,16.9) 14,15.705 13.695,15.4 13.488,15.4 U2.8@13.15,15.4 ; v1@14.246,16.9 C2.2@14.95,16.9 ; v1(28.775,18.616) 28.775,19.864 29.103,20.191 C3.2@29.65,20.191 ; C3.2@29.834,20.187 C4.2@30.784,20.187 30.759,20.212 30.759,21.149 31.21,21.6 33.1,21.6 33.959,20.741 33.959,19.802 U1.3@33.984,19.777
  Bottom Layer w0.25: v1(14,16.9) 14.875,17.775 27.934,17.775 v1(28.775,18.616) 28.765,18.627 28.765,20.04 30.322,21.597 38.853,21.597 40.959,19.491 40.959,18.722 SB19.2@41.659,18.022
5V: C12.2 C13.2 CN1.6 CN1.15 R10.1 SB21.2 U8.1 U8.6 | length 74.5
  Top Layer w0.25: CN1.15@1.27,16 CN1.6@3.27,14 ; v1(34.975,13.375) 36.325,13.375 37.525,12.175 41.6,12.175 41.865,12.44 42.459,13.034 42.459,16.947 44.909,19.397 v1@46.584,21.072 ; R10.1@44.88,21.072 v1(46.484,21.072) v1@46.584,21.072 ; U8.6@49.984,16.097 50.522,16.097 51.375,16.95 51.375,19.692 51.35,19.717 49.989,19.717 C13.2@49.959,19.747 ; U8.1@49.984,18.697 49.959,18.722 C13.2@49.959,19.747 ; v1@46.584,21.072 49.074,21.072 49.897,20.25 49.897,19.81 C13.2@49.959,19.747
  Bottom Layer w0.25: CN1.6@3.27,14 3.326,14 6.314,11.013 9.233,11.013 9.571,11.35 14.619,11.35 18.269,7.7 20.634,7.7 20.684,7.75 20.718,7.75 23.543,10.575 ; 23.557,10.575 25.313,10.575 27.765,13.027 27.773,13.027 27.776,13.03 34.654,13.03 34.975,13.352 v1(34.975,13.375) ; SB21.2@42.719,21.072 v1(46.484,21.072)
BOOT0: R4.2 U4.22 | length 2.5
  Top Layer w0.2: U4.22@30.65,9.675 30.65,11.05 31.22,11.62 31.22,11.72 R4.2@31.375,11.875
E3V3: CN5.2 SB20.1 | length 11.8
  Bottom Layer w0.25: CN5.2@31.859,24.229 34.038,22.05 39.231,22.05 SB20.1@41.734,19.547
E5V: CN4.2 SB21.1 | length 8.1
  Bottom Layer w0.25: CN4.2@35.484,24.229 39.578,24.229 41.734,22.072 SB21.1@41.734,21.072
